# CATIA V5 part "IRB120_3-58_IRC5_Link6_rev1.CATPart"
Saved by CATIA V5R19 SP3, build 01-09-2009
Part number: Link6
Revision: ANY
Definition: UNKNOWN
Nomenclature: Link6
Source: Unknown
Bounding box of the stored display mesh (mm): x 361 to 374, y -20 to 20, z 610 to 650
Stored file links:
  Z:\Projects\ABB_Robotics\ABB LIB\V5\V5PARTS\ABB\120\IRB120_3-58_IRC5_Link6_rev1.CATPart
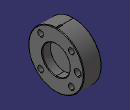
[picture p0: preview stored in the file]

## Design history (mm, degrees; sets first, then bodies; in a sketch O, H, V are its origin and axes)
Body1 "NONE" (main body)
  Solid1: solid without history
